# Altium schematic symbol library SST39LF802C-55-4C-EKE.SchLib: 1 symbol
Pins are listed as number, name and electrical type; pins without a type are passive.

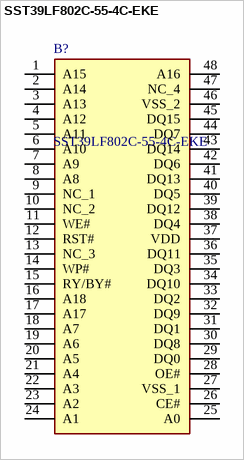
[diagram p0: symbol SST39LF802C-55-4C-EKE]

## SST39LF802C-55-4C-EKE
designator B?
FLASH Memory IC 8Mbit Parallel 55 ns 48-TSOP 3V ~ 3.6V,55 ns,10s 0C ~ 70C (TA); Manufacturer_Name: Microchip; Geometry.Height: 1.2mm
footprint SOP50P2000X120-48N
pins: 1 A15, 2 A14, 3 A13, 4 A12, 5 A11, 6 A10, 7 A9, 8 A8, 9 NC_1, 10 NC_2, 11 WE#, 12 RST#, 13 NC_3, 14 WP#, 15 RY/BY#, 16 A18, 17 A17, 18 A7, 19 A6, 20 A5, 21 A4, 22 A3, 23 A2, 24 A1, 25 A0, 26 CE#, 27 VSS_1, 28 OE#, 29 DQ0, 30 DQ8, 31 DQ1, 32 DQ9, 33 DQ2, 34 DQ10, 35 DQ3, 36 DQ11, 37 VDD, 38 DQ4, 39 DQ12, 40 DQ5, 41 DQ13, 42 DQ6, 43 DQ14, 44 DQ7, 45 DQ15, 46 VSS_2, 47 NC_4, 48 A16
